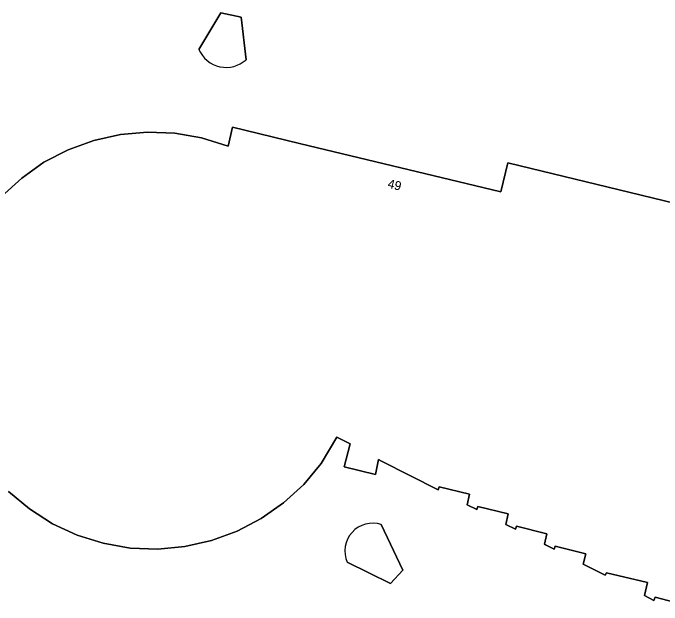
# Model space of a CAD drawing. Extents: x 163043 to 165076, y 382019 to 382874.
# Drawn here: x 163127.5 to 163199.7, y 382491.1 to 382556.9 of the extents above; entities that cross this region are included whole.
import ezdxf

# ---------------------------------------------------------------- set-up
doc = ezdxf.new("R2010")
doc.units = 0
for name, color, linetype in [('IMGEO_Erf', 7, 'Continuous'), ('IMGEO_Muur', 7, 'Continuous'), ('IMGEO_Pand', 7, 'Continuous'), ('IMGEO_Pand_nummerreeks', 7, 'Continuous')]:
    doc.layers.add(name, color=color, linetype=linetype)

msp = doc.modelspace()

# ---------------------------------------------------------------- linework, layer by layer
at = {"layer": 'IMGEO_Erf'}
for points in [[(163148.21, 382552.877), (163150.657, 382556.935), (163152.903, 382556.473), (163153.47, 382551.73)], [(163126.277, 382536.501), (163128.53, 382538.546), (163130.988, 382540.316), (163133.679, 382541.715), (163136.533, 382542.76), (163139.506, 382543.413), (163142.521, 382543.677), (163145.556, 382543.558), (163148.525, 382543.034), (163151.461, 382542.121), (163151.956, 382544.216), (163159.389, 382542.425), (163181.777, 382537.029), (163182.561, 382540.251), (163228.254, 382529.154)], [(163202.304, 382491.058), (163198.934, 382491.917), (163198.808, 382491.569), (163197.749, 382492.112), (163198.088, 382493.564), (163193.531, 382494.628), (163193.394, 382494.364), (163190.96, 382495.612), (163191.223, 382496.77), (163187.819, 382497.605), (163187.71, 382497.272), (163186.767, 382497.751), (163186.644, 382497.814), (163186.918, 382498.976), (163183.538, 382499.816), (163183.419, 382499.485), (163182.349, 382500.028), (163182.623, 382501.19), (163179.243, 382502.03), (163179.12, 382501.687), (163178.036, 382502.225), (163178.307, 382503.375), (163174.927, 382504.215), (163174.808, 382503.884), (163168.517, 382507.072), (163168.185, 382507.24), (163167.852, 382505.571), (163164.385, 382506.43), (163165.024, 382508.995), (163163.567, 382509.723), (163161.822, 382506.819), (163159.874, 382504.477), (163157.637, 382502.43), (163155.14, 382500.682), (163152.463, 382499.267), (163149.608, 382498.235), (163146.649, 382497.559), (163143.65, 382497.29), (163140.582, 382497.395), (163137.579, 382497.941), (163134.677, 382498.844), (163131.952, 382500.11), (163129.377, 382501.744), (163127.048, 382503.699)], [(163168.499, 382500.001), (163170.903, 382494.92), (163169.522, 382493.445), (163164.72, 382495.813)]]:
    msp.add_lwpolyline(points, dxfattribs=at)
for centre, radius, start, end in [((163151.252, 382554.194), 3.315, 203.40715, 311.99005), ((163167.535, 382497.072), 3.084, 71.78618, 204.09142)]:
    msp.add_arc(centre, radius, start, end, dxfattribs=at)
at = {"layer": 'IMGEO_Muur'}
for points in [[(163148.21, 382552.877), (163150.657, 382556.935), (163152.903, 382556.473), (163153.47, 382551.73)], [(163168.499, 382500.001), (163170.903, 382494.92), (163169.522, 382493.445), (163164.72, 382495.813)]]:
    msp.add_lwpolyline(points, dxfattribs=at)
for centre, radius, start, end in [((163151.252, 382554.194), 3.315, 203.40715, 311.99005), ((163167.535, 382497.072), 3.084, 71.78618, 204.09142)]:
    msp.add_arc(centre, radius, start, end, dxfattribs=at)
at = {"layer": 'IMGEO_Pand'}
for points in [[(163152.903, 382556.473), (163150.657, 382556.935), (163148.21, 382552.877)], [(163153.47, 382551.73), (163152.903, 382556.473)], [(163228.254, 382529.154), (163182.561, 382540.251), (163181.777, 382537.029), (163159.389, 382542.425), (163151.956, 382544.216), (163151.461, 382542.121), (163148.525, 382543.034), (163145.556, 382543.558), (163142.521, 382543.677), (163139.506, 382543.413), (163136.533, 382542.76), (163133.679, 382541.715), (163130.988, 382540.316), (163128.53, 382538.546), (163126.277, 382536.501)], [(163127.048, 382503.699), (163129.377, 382501.744), (163131.952, 382500.11), (163134.677, 382498.844), (163137.579, 382497.941), (163140.582, 382497.395), (163143.65, 382497.29), (163146.649, 382497.559), (163149.608, 382498.235), (163152.463, 382499.267), (163155.14, 382500.682), (163157.637, 382502.43), (163159.874, 382504.477), (163161.822, 382506.819), (163163.567, 382509.723), (163165.024, 382508.995), (163164.385, 382506.43), (163167.852, 382505.571), (163168.185, 382507.24), (163168.517, 382507.072), (163174.808, 382503.884), (163174.927, 382504.215), (163178.307, 382503.375), (163178.036, 382502.225), (163179.12, 382501.687), (163179.243, 382502.03), (163182.623, 382501.19), (163182.349, 382500.028), (163183.419, 382499.485), (163183.538, 382499.816), (163186.918, 382498.976), (163186.644, 382497.814), (163186.767, 382497.751), (163187.71, 382497.272), (163187.819, 382497.605), (163191.223, 382496.77), (163190.96, 382495.612), (163193.394, 382494.364), (163193.531, 382494.628), (163198.088, 382493.564), (163197.749, 382492.112), (163198.808, 382491.569), (163198.934, 382491.917), (163202.304, 382491.058)], [(163164.72, 382495.813), (163169.522, 382493.445), (163170.903, 382494.92), (163168.499, 382500.001)]]:
    msp.add_lwpolyline(points, dxfattribs=at)
for centre, radius, start, end in [((163151.252, 382554.194), 3.315, 203.40715, 311.99005), ((163167.535, 382497.072), 3.084, 71.78618, 204.09142)]:
    msp.add_arc(centre, radius, start, end, dxfattribs=at)

# ---------------------------------------------------------------- texts
at = {"layer": 'IMGEO_Pand_nummerreeks'}
msp.add_text('49', height=1, rotation=346.44955, dxfattribs=at).set_placement((163169.142, 382537.503))

doc.saveas('drawing.dxf')
